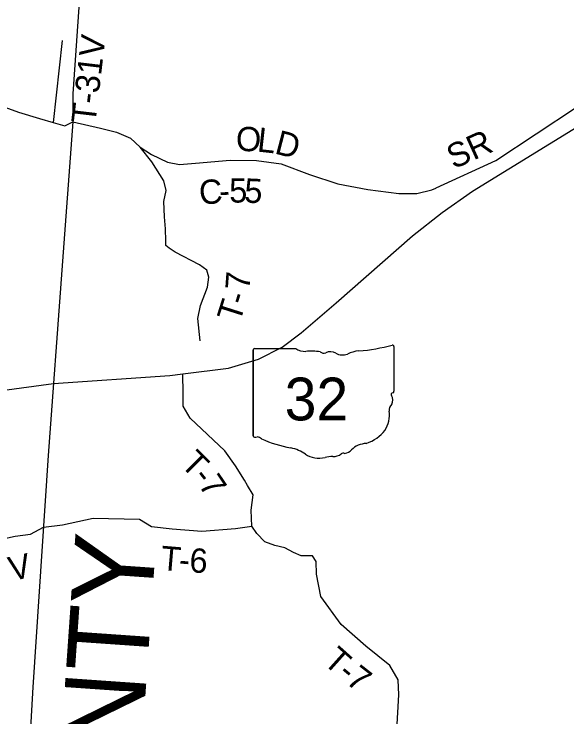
# Model space of a CAD drawing. Extents: x -84548 to 2262448, y -162180 to 525962.
# Drawn here: x -29387 to -22558, y 150992 to 159669 of the extents above; entities that cross this region are included whole.
import ezdxf

# ---------------------------------------------------------------- set-up
doc = ezdxf.new("R2010")
doc.units = 0
for name, color, linetype in [('GM_X_City_Street_Text', 7, 'Continuous'), ('GM_X_County_Road', 7, 'Continuous'), ('GM_X_Major_Lake', 7, 'Continuous'), ('GM_X_Major_Lake_Text', 7, 'Continuous'), ('GM_X_Minor_Lake', 7, 'Continuous'), ('GM_X_Minor_River_Text', 7, 'Continuous'), ('GM_X_Rail_Line', 7, 'Continuous'), ('GM_X_Township_Road', 7, 'Continuous')]:
    doc.layers.add(name, color=color, linetype=linetype)

msp = doc.modelspace()

# ---------------------------------------------------------------- linework, layer by layer
at = {"layer": 'GM_X_Major_Lake'}
for p, q in [((-28556.6, 160201.1), (-28662.7, 158686.2)), ((-28662.7, 158686.2), (-28663, 158340.2)), ((-28663, 158340.2), (-28796.9, 156507.9)), ((-28796.9, 156507.9), (-28965, 154221.2)), ((-28965, 154221.2), (-29155.2, 151361.1)), ((-29155.2, 151361.1), (-29360.1, 147906.7))]:
    msp.add_line(p, q, dxfattribs=at)
at = {"layer": 'GM_X_Major_Lake_Text'}
for points in [[(-28899.8, 155108.1), (-27464.2, 155205.7), (-27301.6, 155226.2), (-26739.3, 155297), (-26369, 155407.8), (-26074.8, 155558.6), (-25840.7, 155735.4), (-25406.6, 156102.9), (-24466.4, 156932.2), (-24098.3, 157219.4), (-23724.1, 157482.5), (-22326.5, 158341.7)], [(-36946.5, 154204.3), (-36866.6, 154250), (-36383.1, 154377.9), (-36020.6, 154398.2), (-35070.9, 154484.9), (-33656.3, 154614.1), (-32749.4, 154696.6), (-30270.8, 154922.1), (-28899.8, 155108.1)]]:
    msp.add_lwpolyline(points, dxfattribs=at)
at = {"layer": 'GM_X_Minor_Lake'}
for points in [[(-28792.6, 159341.6), (-28905.9, 158331.9)], [(-27090.1, 155636.4), (-27116.4, 155909.1), (-27084.4, 156069.6), (-26996.3, 156296.2), (-26982.4, 156422.6), (-27006.5, 156506.8), (-27096.8, 156572.9), (-27395.6, 156729.1), (-27469.7, 156779.8), (-27513.2, 156811.5), (-27512, 156869.4), (-27518.1, 157017.8), (-27530.2, 157166.1), (-27538.4, 157354.6), (-27508.4, 157493), (-27538.5, 157609.3), (-27685, 157845.8), (-27827.5, 158026.2)], [(-26502, 153849.1), (-26503.1, 153851), (-26539.7, 153914.2), (-26650.1, 154092.6), (-26784.5, 154275), (-27211.9, 154681.8), (-27298.2, 154828.2), (-27300.3, 154986.6), (-27301.6, 155226.2)], [(-24676.7, 150538.2), (-24633.1, 151264.2), (-24643.2, 151448.7), (-24743.6, 151625.1), (-25042.5, 151865.6), (-25345.5, 152134.1), (-25598.3, 152478.9), (-25652.7, 152753.6), (-25656.8, 152910), (-25700.9, 152982.2), (-25783.1, 152982.2), (-25839.3, 152982.1), (-25935.5, 153020.2), (-26043.9, 153078.3), (-26166.2, 153108.3), (-26288.5, 153154.3), (-26388.9, 153256.5), (-26449.1, 153346.7), (-26457.2, 153545.3), (-26435.3, 153733.8), (-26502, 153849.1)], [(-29024.1, 153332.6), (-28787, 153363.4), (-28408.1, 153443.8), (-27836.6, 153434.1), (-27690.2, 153344), (-27433.5, 153312), (-27068.6, 153284.2), (-26653.6, 153318.5), (-26449.1, 153346.7)], [(-31035, 152464.4), (-30913.8, 152715), (-30635.4, 153246.1), (-30571.8, 153358.4), (-30539.9, 153402.5), (-30489.9, 153406.7), (-30271.6, 153359.1), (-30137.4, 153319.4), (-29908.9, 153215.9), (-29758.6, 153154.2), (-29668.5, 153144.5), (-29540.6, 153186.8), (-29372.6, 153223.3), (-29182.6, 153249.8), (-29024.1, 153332.6)]]:
    msp.add_lwpolyline(points, dxfattribs=at)
at = {"layer": 'GM_X_Minor_River_Text'}
for points in [[(-24178, 157520.9), (-24172.9, 157523.3), (-23434.2, 157860.4), (-22439.8, 158520.4), (-21822.4, 158946.7)], [(-30475.1, 158556.9), (-30399.2, 158625.1), (-30297.4, 158689.4), (-30263.3, 158701.1), (-30230.8, 158707.5), (-30149.5, 158711.1), (-30095.8, 158706.3), (-30044, 158694.7), (-29961.1, 158672.2), (-29762.8, 158618.7), (-29596.5, 158551.1), (-29332, 158457.7), (-29071.6, 158378.3), (-28905.9, 158331.9), (-28759.1, 158291), (-28663, 158340.2)], [(-28663, 158340.2), (-28319.9, 158261.4), (-28119.7, 158212.6), (-27949.8, 158136.9), (-27827.5, 158026.2), (-27691.1, 157934), (-27492.6, 157839.9), (-27342.1, 157809.9), (-27147.7, 157830.1), (-26716.6, 157866.4), (-26393.8, 157862.6), (-26089, 157820.7), (-25736, 157686.6), (-25389, 157572.5), (-25016, 157504.5), (-24633, 157452.6), (-24412.5, 157452.8), (-24226, 157499), (-24178, 157520.9)]]:
    msp.add_lwpolyline(points, dxfattribs=at)
at = {"layer": 'GM_X_Rail_Line'}
for p, q in [((-26435.1, 155520.7), (-26435.1, 154464.1)), ((-26435.1, 154464.1), (-26435.1, 155520.7)), ((-26435.1, 154464.1), (-26435.1, 155520.7)), ((-26417.9, 155538.9), (-25908.3, 155538.9)), ((-24694.9, 155565.1), (-24694.9, 155012.3)), ((-24695, 155012.5), (-24694.9, 155012.3))]:
    msp.add_line(p, q, dxfattribs=at)
for centre, major_axis, start_param, end_param in [((-26415.1, 155523), (20.2, 0), 1.712693, 3.28349), ((-25786.9, 155661.6), (195.5, 0), 4.042523, 4.731795), ((-25722.1, 154945.7), (702, 0), 1.404758, 1.657858), ((-25479.9, 155406.3), (117.3, 0), 0.950623, 2.079405), ((-25079.4, 155216.2), (371.3, 0), 1.699011, 2.107814), ((-25314.8, 156979.4), (1845.5, 0), 4.814394, 5.042369), ((-24714.2, 155567.4), (19.4, 0), 6.141152, 7.989035), ((-25562.7, 155528.4), (56.4, 0), 3.836095, 5.185415), ((-25328.5, 155573.8), (141.1, 0), 4.081561, 5.145723), ((-24699.3, 154971.8), (30, 0), 1.883978, 3.671073), ((-24715.5, 155010.2), (20.7, 0), 5.05454, 6.418171), ((-24890.1, 154901.9), (180, 0), 5.934695, 6.695948), ((-24625.5, 154781), (130.9, 0), 2.387724, 3.262537), ((-25211.4, 154710.7), (461.6, 0), 5.101752, 6.440018), ((-26415, 154461.8), (20.3, 0), 3.00124, 4.508301), ((-26411.9, 154569.9), (155.2, 0), 4.665946, 4.897461), ((-26380.1, 154403.1), (56, 0), 0.519207, 1.627899), ((-25673.5, 155352.5), (1332.7, 0), 4.195997, 4.488961), ((-26070.8, 153989.4), (417, 0), 0.823519, 1.323587), ((-25337, 154361.7), (149.1, 0), 4.937069, 5.64225), ((-25016.7, 154167.4), (252.8, 0), 1.647645, 2.488434), ((-25619.9, 154397.9), (264.6, 0), 4.026481, 4.996735), ((-25467, 154032.6), (217.4, 0), 1.495662, 1.94098), ((-25447.7, 154318.7), (141, 0), 4.691044, 5.507374), ((-25320.1, 154216.4), (39.7, 0), 1.147584, 2.315152)]:
    msp.add_ellipse(centre, major_axis=major_axis, ratio=0.8, start_param=start_param, end_param=end_param, dxfattribs=at)

# ---------------------------------------------------------------- texts
at = {"layer": 'GM_X_City_Street_Text'}
msp.add_text('MEIGS  COUNTY', height=1000, rotation=86.01767, dxfattribs=at).set_placement((-28371.5, 142543.7))
at = {"layer": 'GM_X_County_Road'}
for s, rotation, p in [('O', 358.2366, (-26650.1, 157980.7)), ('L', 353.66596, (-26392.6, 157973)), ('D', 345.42526, (-26180.7, 157950.3)), ('SR', 24.3048, (-23956.8, 157750.6)), ('C', 4.16028, (-27092, 157315.8)), ('5', 0.69216, (-26728, 157340.6)), ('5', 357.19399, (-26548.1, 157342.9)), ('-', 3.29587, (-26847.4, 157333.6))]:
    msp.add_text(s, height=300, rotation=rotation, dxfattribs=at).set_placement(p)
at = {"layer": 'GM_X_Rail_Line'}
msp.add_text('32', height=528, dxfattribs=at).set_placement((-26044.7, 154652.8))
at = {"layer": 'GM_X_Township_Road'}
for s, rotation, p in [('T-31V', 83.28992, (-28383.5, 158307.2)), ('7', 85.99444, (-26479.4, 156256)), ('-', 72.15749, (-26531.8, 156062.6)), ('T', 72.41818, (-26599.5, 155849)), ('T', 314.81969, (-27342.3, 154101.7)), ('-', 308.15022, (-27190.2, 153949.4)), ('7', 304.13463, (-27117.4, 153857)), ('T', 355.22034, (-27583.4, 152806.7)), ('6', 357.07694, (-27226.4, 152777.7)), ('V', 12.38057, (-29418.4, 152666.4)), ('-', 355.49952, (-27358.2, 152787.9)), ('T', 318.16681, (-25580.6, 151658.8)), ('7', 322.061, (-25301.8, 151416.4)), ('-', 320.26969, (-25404.4, 151501.4))]:
    msp.add_text(s, height=300, rotation=rotation, dxfattribs=at).set_placement(p)

doc.saveas('drawing.dxf')
